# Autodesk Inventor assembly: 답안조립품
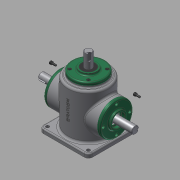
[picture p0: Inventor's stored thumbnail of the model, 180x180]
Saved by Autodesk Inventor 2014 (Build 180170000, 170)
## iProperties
Created: 2015-10
Part Number: 답안조립품
Document SubType Name: Assembly
Designer: USER
Author: USER
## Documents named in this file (12)
- C:\Users\USER\Desktop\451007V1015\답안조립품.iam
- C:\Users\USER\Desktop\451007V1015\본체.ipt
- C:\Users\USER\Desktop\451007V1015\베어링 6203.ipt
- C:\Users\USER\Desktop\451007V1015\커버.ipt
- C:\Users\USER\Desktop\451007V1015\서브 축.ipt
- 서브 축.ipt
- C:\Users\USER\Desktop\451007V1015\키 4x4.ipt
- C:\Users\USER\Desktop\451007V1015\M4.ipt
- C:\Users\USER\Desktop\451007V1015\오일실.ipt
- C:\Users\USER\Desktop\451007V1015\메인 축.ipt
- 메인 축.ipt
- C:\Users\USER\Desktop\451007V1015\키 5x5.ipt
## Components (6 placed, 1 different names)
1. M4:5
2. M4:6
3. M4:1
4. M4:2
5. M4:3
6. M4:4
## Named parameters: d16_d13 = 0, d17_d14 = 0, d18_d15 = 0, d19_d11 = 0
